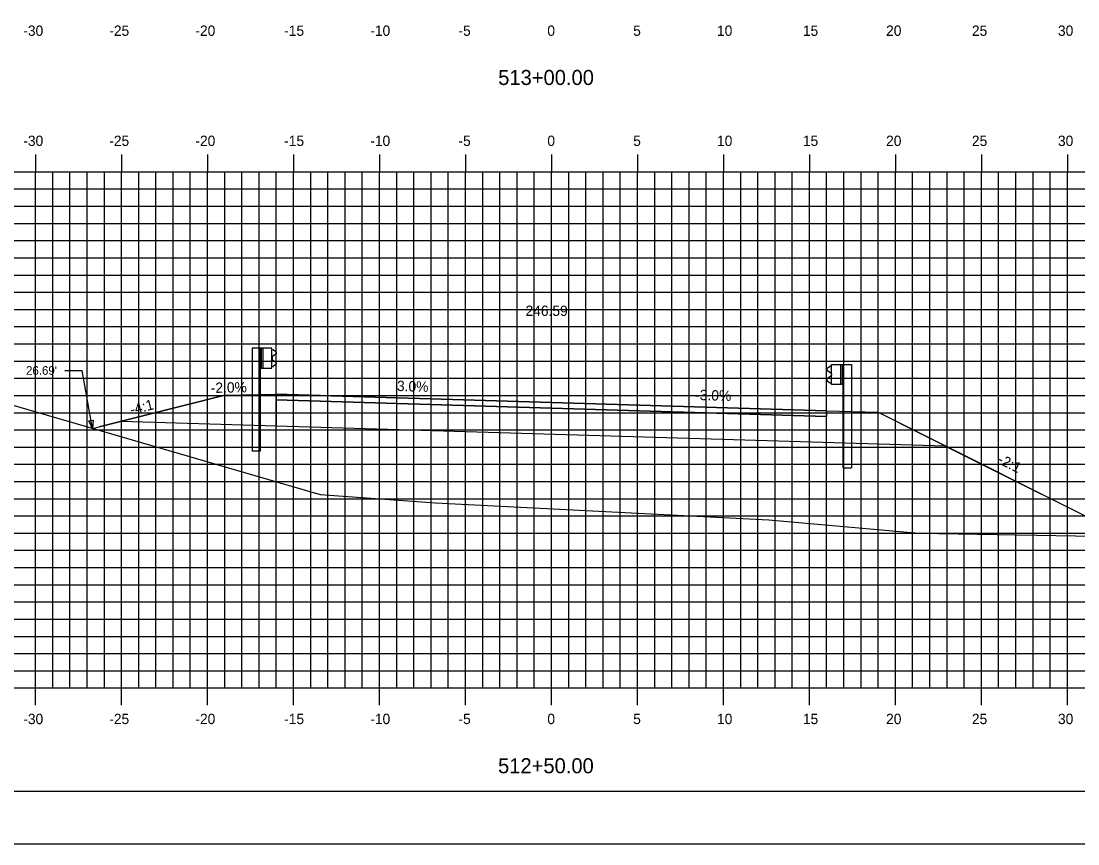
# Model space of a CAD drawing. Extents: x 1170543 to 1177585, y 609599 to 610623.
# Drawn here: x 1172665.2 to 1172726.6, y 609598.8 to 609646.6 of the extents above; entities that cross this region are included whole.
import ezdxf

# ---------------------------------------------------------------- set-up
doc = ezdxf.new("R2010")
doc.units = 0
for name, color, linetype in [('ANNOTATION', 7, 'Continuous'), ('BORDER', 7, 'Continuous'), ('D_Guardrail_Beam_Lt', 7, 'Continuous'), ('D_Guardrail_Beam_Rt', 7, 'Continuous'), ('D_Roadway_Centerline', 7, 'Continuous'), ('D_Roadway_Centerline_Text', 7, 'Continuous'), ('D_Roadway_Edge_Shoulder', 7, 'Continuous'), ('D_Roadway_Edge_TW', 7, 'Continuous'), ('D_Roadway_Pavement', 7, 'Continuous'), ('D_Roadway_SlopeLines', 7, 'Continuous'), ('D_Roadway_SubGrade', 7, 'Continuous'), ('H_V ANNOTATION', 7, 'Continuous'), ('MAJOR', 7, 'Continuous'), ('MINOR', 7, 'Continuous'), ('PLOT BOUNDARY', 7, 'Continuous'), ('S_Roadway_Centerline', 7, 'Continuous'), ('SHADING', 7, 'Continuous')]:
    doc.layers.add(name, color=color, linetype=linetype)

msp = doc.modelspace()

# ---------------------------------------------------------------- linework, layer by layer
at = {"layer": 'ANNOTATION'}
for p in [(1172667.697, 609626.324), (1172669.298, 609622.931)]:
    msp.add_line(p, (1172668.697, 609626.324), dxfattribs=at)
msp.add_lwpolyline([(1172669.334, 609623.445), (1172669.298, 609622.931), (1172669.087, 609623.401)], close=True, dxfattribs=at)
at = {"layer": 'BORDER'}
msp.add_line((1172620.991, 609601.872), (1172780.991, 609601.872), dxfattribs=at)
at = {"layer": 'D_Guardrail_Beam_Lt'}
for p, q in [((1172678.578, 609627.629), (1172678.578, 609621.629)), ((1172679.048, 609627.629), (1172678.578, 609627.629)), ((1172679.736, 609627.629), (1172679.048, 609627.629)), ((1172679.048, 609627.629), (1172679.048, 609626.462)), ((1172679.111, 609627.629), (1172679.111, 609626.462)), ((1172679.215, 609627.629), (1172679.215, 609626.462)), ((1172679.736, 609626.462), (1172679.736, 609627.629)), ((1172679.736, 609627.545), (1172679.81, 609627.531)), ((1172679.969, 609627.281), (1172679.774, 609627.145)), ((1172679.826, 609627.524), (1172679.969, 609627.424)), ((1172679.81, 609626.56), (1172679.736, 609626.545)), ((1172679.74, 609627.08), (1172679.74, 609627.01)), ((1172679.774, 609626.946), (1172679.969, 609626.81)), ((1172679.969, 609626.667), (1172679.826, 609626.567)), ((1172679.048, 609626.462), (1172679.736, 609626.462)), ((1172679.069, 609621.629), (1172679.069, 609626.462)), ((1172679.069, 609621.629), (1172678.578, 609621.629))]:
    msp.add_line(p, q, dxfattribs=at)
for centre, major_axis, start_param, end_param in [((1172679.802, 609627.49), (0.0417, 0), 0.959931, 1.376053), ((1172679.919, 609627.353), (0.0877, 0), 5.323254, 7.243116), ((1172679.819, 609627.08), (-0.0789, 0), 5.323254, 6.283185), ((1172679.819, 609627.01), (-0.0789, 0), 6.283185, 7.243116), ((1172679.802, 609626.601), (0.0417, 0), 4.907132, 5.323254), ((1172679.919, 609626.738), (0.0877, 0), 5.323254, 7.243116)]:
    msp.add_ellipse(centre, major_axis=major_axis, ratio=0.995501, start_param=start_param, end_param=end_param, dxfattribs=at)
at = {"layer": 'D_Guardrail_Beam_Rt'}
for p, q in [((1172712.187, 609626.564), (1172712.044, 609626.464)), ((1172712.277, 609626.585), (1172712.203, 609626.571)), ((1172712.277, 609626.669), (1172712.965, 609626.669)), ((1172712.277, 609625.502), (1172712.277, 609626.669)), ((1172712.798, 609626.669), (1172712.798, 609625.502)), ((1172712.902, 609626.669), (1172712.902, 609625.502)), ((1172712.965, 609626.669), (1172713.436, 609626.669)), ((1172712.965, 609626.669), (1172712.965, 609625.502)), ((1172713.436, 609626.669), (1172713.436, 609620.669)), ((1172712.044, 609626.321), (1172712.239, 609626.185)), ((1172712.239, 609625.986), (1172712.044, 609625.85)), ((1172712.273, 609626.12), (1172712.273, 609626.05)), ((1172712.044, 609625.707), (1172712.187, 609625.607)), ((1172712.203, 609625.6), (1172712.277, 609625.585)), ((1172712.965, 609625.502), (1172712.277, 609625.502)), ((1172712.944, 609620.669), (1172712.944, 609625.502)), ((1172712.944, 609620.669), (1172713.436, 609620.669))]:
    msp.add_line(p, q, dxfattribs=at)
for centre, major_axis, start_param, end_param in [((1172712.211, 609626.53), (-0.0417, 0), 4.907132, 5.323254), ((1172712.094, 609626.393), (-0.0877, 0), 5.323254, 7.243116), ((1172712.194, 609626.12), (0.0789, 0), 0, 0.959931), ((1172712.194, 609626.05), (0.0789, 0), 5.323254, 6.283185), ((1172712.094, 609625.778), (-0.0877, 0), 5.323254, 7.243116), ((1172712.211, 609625.641), (-0.0417, 0), 0.959931, 1.376053)]:
    msp.add_ellipse(centre, major_axis=major_axis, ratio=0.995501, start_param=start_param, end_param=end_param, dxfattribs=at)
at = {"layer": 'D_Roadway_Centerline'}
msp.add_lwpolyline([(1172669.298, 609622.96), (1172669.69, 609623.058), (1172676.991, 609624.883), (1172679.991, 609624.943), (1172695.991, 609624.463), (1172711.991, 609623.983), (1172714.991, 609623.893), (1172719.956, 609621.411), (1172729.12, 609616.829)], dxfattribs=at)
at = {"layer": 'D_Roadway_Edge_Shoulder'}
for points in [[(1172679.991, 609624.943), (1172679.991, 609624.61)], [(1172711.991, 609623.983), (1172711.991, 609623.65)]]:
    msp.add_lwpolyline(points, dxfattribs=at)
at = {"layer": 'D_Roadway_Edge_TW'}
msp.add_lwpolyline([(1172711.991, 609623.65), (1172711.991, 609623.983), (1172695.991, 609624.463), (1172679.991, 609624.943), (1172679.991, 609624.61), (1172695.991, 609624.13)], close=True, dxfattribs=at)
at = {"layer": 'D_Roadway_Pavement'}
msp.add_lwpolyline([(1172711.991, 609623.65), (1172711.991, 609623.65), (1172695.991, 609624.13), (1172679.991, 609624.61), (1172679.991, 609624.61), (1172695.991, 609624.13)], close=True, dxfattribs=at)
for points in [[(1172679.991, 609624.61), (1172679.991, 609624.61)], [(1172679.991, 609624.61), (1172679.991, 609624.61)], [(1172711.991, 609623.65), (1172711.991, 609623.65)], [(1172711.991, 609623.65), (1172711.991, 609623.65)]]:
    msp.add_lwpolyline(points, dxfattribs=at)
at = {"layer": 'D_Roadway_SlopeLines'}
for points in [[(1172676.991, 609624.883), (1172669.69, 609623.058)], [(1172714.991, 609623.893), (1172729.435, 609616.671)]]:
    msp.add_lwpolyline(points, dxfattribs=at)
at = {"layer": 'D_Roadway_SubGrade'}
for p, q in [((1172669.298, 609622.96), (1172676.991, 609624.883)), ((1172676.991, 609624.883), (1172679.991, 609624.943)), ((1172679.991, 609624.943), (1172679.991, 609623.11)), ((1172695.991, 609624.13), (1172679.991, 609624.61)), ((1172679.991, 609624.61), (1172679.991, 609623.11)), ((1172711.991, 609623.65), (1172695.991, 609624.13)), ((1172711.991, 609623.983), (1172714.991, 609623.893)), ((1172711.991, 609622.15), (1172711.991, 609623.983)), ((1172711.991, 609622.15), (1172711.991, 609623.65)), ((1172714.991, 609623.893), (1172719.956, 609621.411)), ((1172669.298, 609622.931), (1172669.298, 609622.96))]:
    msp.add_line(p, q, dxfattribs=at)
at = {"layer": 'MAJOR'}
for p, q in [((1172665.991, 609638.874), (1172665.991, 609637.872)), ((1172670.991, 609638.874), (1172670.991, 609637.872)), ((1172675.991, 609638.874), (1172675.991, 609637.872)), ((1172680.991, 609638.874), (1172680.991, 609637.872)), ((1172685.991, 609638.874), (1172685.991, 609637.872)), ((1172690.991, 609638.874), (1172690.991, 609637.872)), ((1172695.991, 609638.874), (1172695.991, 609637.872)), ((1172700.991, 609638.874), (1172700.991, 609637.872)), ((1172705.991, 609638.874), (1172705.991, 609637.872)), ((1172710.991, 609638.874), (1172710.991, 609637.872)), ((1172715.991, 609638.874), (1172715.991, 609637.872)), ((1172720.991, 609638.874), (1172720.991, 609637.872)), ((1172725.991, 609638.874), (1172725.991, 609637.872)), ((1172625.991, 609637.872), (1172765.991, 609637.872)), ((1172625.991, 609637.872), (1172765.991, 609637.872)), ((1172665.991, 609607.872), (1172665.991, 609637.872)), ((1172670.991, 609607.872), (1172670.991, 609637.872)), ((1172675.991, 609607.872), (1172675.991, 609637.872)), ((1172680.991, 609607.872), (1172680.991, 609637.872)), ((1172685.991, 609607.872), (1172685.991, 609637.872)), ((1172690.991, 609607.872), (1172690.991, 609637.872)), ((1172695.991, 609607.872), (1172695.991, 609637.872)), ((1172700.991, 609607.872), (1172700.991, 609637.872)), ((1172705.991, 609607.872), (1172705.991, 609637.872)), ((1172710.991, 609607.872), (1172710.991, 609637.872)), ((1172715.991, 609607.872), (1172715.991, 609637.872)), ((1172720.991, 609607.872), (1172720.991, 609637.872)), ((1172725.991, 609607.872), (1172725.991, 609637.872)), ((1172625.991, 609632.872), (1172765.991, 609632.872)), ((1172625.991, 609627.872), (1172765.991, 609627.872)), ((1172625.991, 609622.872), (1172765.991, 609622.872)), ((1172625.991, 609617.872), (1172765.991, 609617.872)), ((1172625.991, 609612.872), (1172765.991, 609612.872)), ((1172625.991, 609607.872), (1172765.991, 609607.872)), ((1172625.991, 609607.872), (1172765.991, 609607.872)), ((1172665.991, 609606.87), (1172665.991, 609607.872)), ((1172670.991, 609606.87), (1172670.991, 609607.872)), ((1172675.991, 609606.87), (1172675.991, 609607.872)), ((1172680.991, 609606.87), (1172680.991, 609607.872)), ((1172685.991, 609606.87), (1172685.991, 609607.872)), ((1172690.991, 609606.87), (1172690.991, 609607.872)), ((1172695.991, 609606.87), (1172695.991, 609607.872)), ((1172700.991, 609606.87), (1172700.991, 609607.872)), ((1172705.991, 609606.87), (1172705.991, 609607.872)), ((1172710.991, 609606.87), (1172710.991, 609607.872)), ((1172715.991, 609606.87), (1172715.991, 609607.872)), ((1172720.991, 609606.87), (1172720.991, 609607.872)), ((1172725.991, 609606.87), (1172725.991, 609607.872))]:
    msp.add_line(p, q, dxfattribs=at)
at = {"layer": 'MINOR'}
for p, q in [((1172666.991, 609607.872), (1172666.991, 609637.872)), ((1172667.991, 609607.872), (1172667.991, 609637.872)), ((1172668.991, 609607.872), (1172668.991, 609637.872)), ((1172669.991, 609607.872), (1172669.991, 609637.872)), ((1172671.991, 609607.872), (1172671.991, 609637.872)), ((1172672.991, 609607.872), (1172672.991, 609637.872)), ((1172673.991, 609607.872), (1172673.991, 609637.872)), ((1172674.991, 609607.872), (1172674.991, 609637.872)), ((1172676.991, 609607.872), (1172676.991, 609637.872)), ((1172677.991, 609607.872), (1172677.991, 609637.872)), ((1172678.991, 609607.872), (1172678.991, 609637.872)), ((1172679.991, 609607.872), (1172679.991, 609637.872)), ((1172681.991, 609607.872), (1172681.991, 609637.872)), ((1172682.991, 609607.872), (1172682.991, 609637.872)), ((1172683.991, 609607.872), (1172683.991, 609637.872)), ((1172684.991, 609607.872), (1172684.991, 609637.872)), ((1172686.991, 609607.872), (1172686.991, 609637.872)), ((1172687.991, 609607.872), (1172687.991, 609637.872)), ((1172688.991, 609607.872), (1172688.991, 609637.872)), ((1172689.991, 609607.872), (1172689.991, 609637.872)), ((1172691.991, 609607.872), (1172691.991, 609637.872)), ((1172692.991, 609607.872), (1172692.991, 609637.872)), ((1172693.991, 609607.872), (1172693.991, 609637.872)), ((1172694.991, 609607.872), (1172694.991, 609637.872)), ((1172696.991, 609607.872), (1172696.991, 609637.872)), ((1172697.991, 609607.872), (1172697.991, 609637.872)), ((1172698.991, 609607.872), (1172698.991, 609637.872)), ((1172699.991, 609607.872), (1172699.991, 609637.872)), ((1172701.991, 609607.872), (1172701.991, 609637.872)), ((1172702.991, 609607.872), (1172702.991, 609637.872)), ((1172703.991, 609607.872), (1172703.991, 609637.872)), ((1172704.991, 609607.872), (1172704.991, 609637.872)), ((1172706.991, 609607.872), (1172706.991, 609637.872)), ((1172707.991, 609607.872), (1172707.991, 609637.872)), ((1172708.991, 609607.872), (1172708.991, 609637.872)), ((1172709.991, 609607.872), (1172709.991, 609637.872)), ((1172711.991, 609607.872), (1172711.991, 609637.872)), ((1172712.991, 609607.872), (1172712.991, 609637.872)), ((1172713.991, 609607.872), (1172713.991, 609637.872)), ((1172714.991, 609607.872), (1172714.991, 609637.872)), ((1172716.991, 609607.872), (1172716.991, 609637.872)), ((1172717.991, 609607.872), (1172717.991, 609637.872)), ((1172718.991, 609607.872), (1172718.991, 609637.872)), ((1172719.991, 609607.872), (1172719.991, 609637.872)), ((1172721.991, 609607.872), (1172721.991, 609637.872)), ((1172722.991, 609607.872), (1172722.991, 609637.872)), ((1172723.991, 609607.872), (1172723.991, 609637.872)), ((1172724.991, 609607.872), (1172724.991, 609637.872)), ((1172625.991, 609636.872), (1172765.991, 609636.872)), ((1172625.991, 609635.872), (1172765.991, 609635.872)), ((1172625.991, 609634.872), (1172765.991, 609634.872)), ((1172625.991, 609633.872), (1172765.991, 609633.872)), ((1172625.991, 609631.872), (1172765.991, 609631.872)), ((1172625.991, 609630.872), (1172765.991, 609630.872)), ((1172625.991, 609629.872), (1172765.991, 609629.872)), ((1172625.991, 609628.872), (1172765.991, 609628.872)), ((1172625.991, 609626.872), (1172765.991, 609626.872)), ((1172625.991, 609625.872), (1172765.991, 609625.872)), ((1172625.991, 609624.872), (1172765.991, 609624.872)), ((1172625.991, 609623.872), (1172765.991, 609623.872)), ((1172625.991, 609621.872), (1172765.991, 609621.872)), ((1172625.991, 609620.872), (1172765.991, 609620.872)), ((1172625.991, 609619.872), (1172765.991, 609619.872)), ((1172625.991, 609618.872), (1172765.991, 609618.872)), ((1172625.991, 609616.872), (1172765.991, 609616.872)), ((1172625.991, 609615.872), (1172765.991, 609615.872)), ((1172625.991, 609614.872), (1172765.991, 609614.872)), ((1172625.991, 609613.872), (1172765.991, 609613.872)), ((1172625.991, 609611.872), (1172765.991, 609611.872)), ((1172625.991, 609610.872), (1172765.991, 609610.872)), ((1172625.991, 609609.872), (1172765.991, 609609.872)), ((1172625.991, 609608.872), (1172765.991, 609608.872))]:
    msp.add_line(p, q, dxfattribs=at)
at = {"layer": 'PLOT BOUNDARY'}
msp.add_lwpolyline([(1172612.898, 609598.813), (1172782.898, 609598.813), (1172782.898, 609708.813), (1172612.898, 609708.813)], close=True, dxfattribs=at)
at = {"layer": 'S_Roadway_Centerline'}
msp.add_lwpolyline([(1172625.991, 609629.633), (1172626.791, 609629.613), (1172629.779, 609629.54), (1172632.644, 609629.463), (1172634.826, 609629.405), (1172635.391, 609629.396), (1172637.628, 609629.343), (1172646.765, 609629.003), (1172647.443, 609628.977), (1172647.498, 609628.971), (1172649.875, 609628.706), (1172664.482, 609624.358), (1172682.535, 609619.117), (1172689.244, 609618.625), (1172708.621, 609617.636), (1172717.348, 609616.878), (1172743.561, 609616.43)], dxfattribs=at)
at = {"layer": 'SHADING'}
msp.add_lwpolyline([(1172670.979, 609623.38), (1172679.991, 609623.11), (1172718.892, 609621.943)], dxfattribs=at)

# ---------------------------------------------------------------- texts
at = {"layer": 'ANNOTATION'}
msp.add_text("26.69'", height=0.5, dxfattribs=at).set_placement((1172665.437, 609626.074))
for s, rotation, p in [('-2.0%', 1.14576, (1172676.187, 609625.015)), ('3.0%', 358.28164, (1172686.999, 609625.133)), ('-3.0%', 358.28164, (1172704.339, 609624.613)), ('-4:1', 14.03624, (1172671.568, 609623.745)), ('-2:1', 333.43495, (1172721.879, 609620.967))]:
    msp.add_text(s, height=0.6, rotation=rotation, dxfattribs=at).set_placement(p)
at = {"layer": 'D_Roadway_Centerline'}
for s, p in [('C', (1172695.986, 609624.463)), ('L', (1172695.991, 609624.456))]:
    msp.add_text(s, height=0.0146, dxfattribs=at).set_placement(p)
at = {"layer": 'D_Roadway_Centerline_Text'}
msp.add_text('246.59', height=0.6, dxfattribs=at).set_placement((1172694.482, 609629.495))
at = {"layer": 'H_V ANNOTATION'}
for s, height, p in [('-30', 0.6, (1172665.279, 609645.772)), ('-25', 0.6, (1172670.277, 609645.772)), ('-20', 0.6, (1172675.285, 609645.772)), ('-15', 0.6, (1172680.448, 609645.772)), ('-10', 0.6, (1172685.456, 609645.772)), ('-5', 0.6, (1172690.582, 609645.772)), ('0', 0.6, (1172695.75, 609645.772)), ('5', 0.6, (1172700.742, 609645.772)), ('10', 0.6, (1172705.616, 609645.772)), ('15', 0.6, (1172710.608, 609645.772)), ('20', 0.6, (1172715.445, 609645.772)), ('25', 0.6, (1172720.437, 609645.772)), ('30', 0.6, (1172725.44, 609645.772)), ('513+00.00', 0.875, (1172692.893, 609642.915)), ('-30', 0.6, (1172665.279, 609639.372)), ('-25', 0.6, (1172670.277, 609639.372)), ('-20', 0.6, (1172675.285, 609639.372)), ('-15', 0.6, (1172680.448, 609639.372)), ('-10', 0.6, (1172685.456, 609639.372)), ('-5', 0.6, (1172690.582, 609639.372)), ('0', 0.6, (1172695.75, 609639.372)), ('5', 0.6, (1172700.742, 609639.372)), ('10', 0.6, (1172705.616, 609639.372)), ('15', 0.6, (1172710.608, 609639.372)), ('20', 0.6, (1172715.445, 609639.372)), ('25', 0.6, (1172720.437, 609639.372)), ('30', 0.6, (1172725.44, 609639.372)), ('-30', 0.6, (1172665.279, 609605.772)), ('-25', 0.6, (1172670.277, 609605.772)), ('-20', 0.6, (1172675.285, 609605.772)), ('-15', 0.6, (1172680.448, 609605.772)), ('-10', 0.6, (1172685.456, 609605.772)), ('-5', 0.6, (1172690.582, 609605.772)), ('0', 0.6, (1172695.75, 609605.772)), ('5', 0.6, (1172700.742, 609605.772)), ('10', 0.6, (1172705.616, 609605.772)), ('15', 0.6, (1172710.608, 609605.772)), ('20', 0.6, (1172715.445, 609605.772)), ('25', 0.6, (1172720.437, 609605.772)), ('30', 0.6, (1172725.44, 609605.772)), ('512+50.00', 0.875, (1172692.885, 609602.915))]:
    msp.add_text(s, height=height, dxfattribs=at).set_placement(p)

doc.saveas('drawing.dxf')
